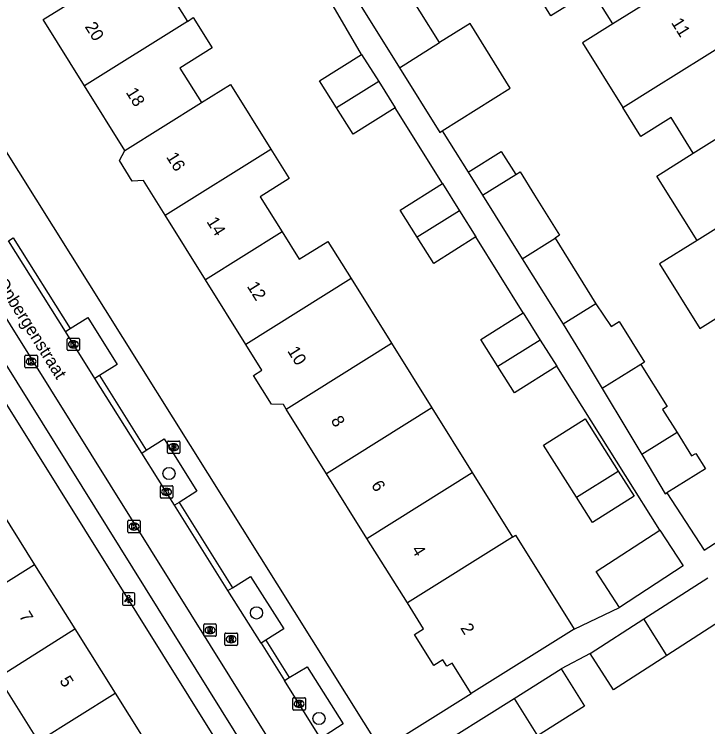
# Model space of a CAD drawing. Extents: x 159353 to 160616, y 385893 to 387321.
# Drawn here: x 159751.8 to 159807.5, y 386153.3 to 386210.6 of the extents above; entities that cross this region are included whole.
import ezdxf

# ---------------------------------------------------------------- set-up
doc = ezdxf.new("R2010")
doc.units = 0
for name, color, linetype in [('IMGEO_Boom', 7, 'Continuous'), ('IMGEO_Brandkraan', 7, 'Continuous'), ('IMGEO_Kolk', 7, 'Continuous'), ('IMGEO_Lichtpunt', 7, 'Continuous'), ('IMGEO_Openbare_ruimte_label', 7, 'Continuous'), ('IMGEO_Pand', 7, 'Continuous'), ('IMGEO_Pand_nummerreeks', 7, 'Continuous'), ('IMGEO_Rijbaan_lokaal_open', 7, 'Continuous'), ('IMGEO_Rioolput', 7, 'Continuous'), ('IMGEO_Voetpad_open', 7, 'Continuous')]:
    doc.layers.add(name, color=color, linetype=linetype)

msp = doc.modelspace()

# ---------------------------------------------------------------- linework, layer by layer
at = {"layer": 'IMGEO_Boom'}
for centre in [(159764.26, 386173.664), (159771.288, 386162.469), (159776.31, 386153.988)]:
    msp.add_circle(centre, 0.489, dxfattribs=at)
at = {"layer": 'IMGEO_Brandkraan'}
for p, q in [((159764.131, 386175.348), (159764.131, 386176.2)), ((159764.206, 386176.274), (159765.058, 386176.274)), ((159764.619, 386176.054), (159764.644, 386176.054)), ((159765.132, 386176.2), (159765.132, 386175.348)), ((159765.058, 386175.274), (159764.206, 386175.274)), ((159764.642, 386175.494), (159764.617, 386175.494))]:
    msp.add_line(p, q, dxfattribs=at)
for points in [[(159764.131, 386175.348), (159764.131, 386176.2)], [(159764.206, 386176.274), (159765.058, 386176.274)], [(159764.479, 386175.974), (159764.479, 386175.574), (159764.692, 386175.574)], [(159764.71, 386175.974), (159764.479, 386175.974)], [(159764.658, 386175.893), (159764.604, 386175.893), (159764.604, 386175.817)], [(159764.604, 386175.817), (159764.657, 386175.817)], [(159765.132, 386176.2), (159765.132, 386175.348)], [(159765.058, 386175.274), (159764.206, 386175.274)], [(159764.666, 386175.741), (159764.604, 386175.741), (159764.604, 386175.66)], [(159764.604, 386175.66), (159764.666, 386175.66)]]:
    msp.add_lwpolyline(points, dxfattribs=at)
for centre, radius, start, end in [((159764.208, 386176.198), 0.0765, 91.552, 178.448), ((159764.208, 386176.198), 0.0765, 91.552, 178.448), ((159764.659, 386175.855), 0.0379, 267.8285, 90.9355), ((159764.714, 386175.829), 0.145, 59.4692, 91.5367), ((159764.739, 386175.876), 0.0922, 285.5137, 58.1501), ((159764.744, 386175.684), 0.105, 301.3115, 78.989), ((159765.056, 386176.198), 0.0765, 1.552, 88.448), ((159765.056, 386176.198), 0.0765, 1.552, 88.448), ((159764.208, 386175.35), 0.0765, 181.552, 268.448), ((159764.208, 386175.35), 0.0765, 181.552, 268.448), ((159764.667, 386175.7), 0.0404, 269.8759, 90.5077), ((159764.698, 386175.825), 0.251, 268.6676, 293.5347), ((159765.056, 386175.35), 0.0765, 271.552, 358.448), ((159765.056, 386175.35), 0.0765, 271.552, 358.448)]:
    msp.add_arc(centre, radius, start, end, dxfattribs=at)
for centre, major_axis, ratio, start_param, end_param in [((159764.618, 386175.774), (-0.387, 0.002), 0.722429, 4.712389, 7.853982), ((159764.643, 386175.774), (-0.39, 0.002), 0.717154, 1.570796, 4.712389)]:
    msp.add_ellipse(centre, major_axis=major_axis, ratio=ratio, start_param=start_param, end_param=end_param, dxfattribs=at)
at = {"layer": 'IMGEO_Kolk'}
for p, q in [((159756.075, 386183.615), (159756.075, 386184.467)), ((159756.15, 386184.541), (159757.002, 386184.541)), ((159757.076, 386184.467), (159757.076, 386183.615)), ((159756.563, 386184.321), (159756.588, 386184.321)), ((159757.002, 386183.541), (159756.15, 386183.541)), ((159756.586, 386183.761), (159756.561, 386183.761)), ((159752.683, 386182.239), (159752.683, 386183.091)), ((159752.758, 386183.165), (159753.61, 386183.165)), ((159753.171, 386182.945), (159753.196, 386182.945)), ((159753.684, 386183.091), (159753.684, 386182.239)), ((159753.61, 386182.165), (159752.758, 386182.165)), ((159753.194, 386182.385), (159753.169, 386182.385)), ((159763.563, 386171.761), (159763.563, 386172.613)), ((159763.638, 386172.687), (159764.49, 386172.687)), ((159764.051, 386172.467), (159764.076, 386172.467)), ((159764.564, 386172.613), (159764.564, 386171.761)), ((159764.074, 386171.907), (159764.049, 386171.907)), ((159764.49, 386171.687), (159763.638, 386171.687)), ((159760.949, 386168.981), (159760.949, 386169.833)), ((159761.024, 386169.907), (159761.876, 386169.907)), ((159761.437, 386169.687), (159761.462, 386169.687)), ((159761.95, 386169.833), (159761.95, 386168.981)), ((159761.876, 386168.907), (159761.024, 386168.907)), ((159761.46, 386169.127), (159761.435, 386169.127)), ((159774.217, 386154.734), (159774.217, 386155.586)), ((159774.292, 386155.66), (159775.144, 386155.66)), ((159774.705, 386155.44), (159774.73, 386155.44)), ((159775.218, 386155.586), (159775.218, 386154.734)), ((159775.144, 386154.66), (159774.292, 386154.66)), ((159774.728, 386154.88), (159774.703, 386154.88))]:
    msp.add_line(p, q, dxfattribs=at)
for points in [[(159756.075, 386183.615), (159756.075, 386184.467)], [(159756.15, 386184.541), (159757.002, 386184.541)], [(159757.076, 386184.467), (159757.076, 386183.615)], [(159756.396, 386184.241), (159756.519, 386184.241), (159756.519, 386184.09), (159756.649, 386184.241), (159756.813, 386184.241), (159756.667, 386184.09), (159756.82, 386183.841), (159756.668, 386183.841), (159756.583, 386184.005), (159756.519, 386183.938), (159756.519, 386183.841), (159756.396, 386183.841), (159756.396, 386184.241)], [(159757.002, 386183.541), (159756.15, 386183.541)], [(159752.683, 386182.239), (159752.683, 386183.091)], [(159752.758, 386183.165), (159753.61, 386183.165)], [(159753.004, 386182.865), (159753.127, 386182.865), (159753.127, 386182.714), (159753.257, 386182.865), (159753.421, 386182.865), (159753.275, 386182.714), (159753.428, 386182.465), (159753.276, 386182.465), (159753.191, 386182.629), (159753.127, 386182.562), (159753.127, 386182.465), (159753.004, 386182.465), (159753.004, 386182.865)], [(159753.684, 386183.091), (159753.684, 386182.239)], [(159753.61, 386182.165), (159752.758, 386182.165)], [(159763.563, 386171.761), (159763.563, 386172.613)], [(159763.638, 386172.687), (159764.49, 386172.687)], [(159763.884, 386172.387), (159764.007, 386172.387), (159764.007, 386172.236), (159764.137, 386172.387), (159764.301, 386172.387), (159764.155, 386172.236), (159764.308, 386171.987), (159764.156, 386171.987), (159764.071, 386172.151), (159764.007, 386172.084), (159764.007, 386171.987), (159763.884, 386171.987), (159763.884, 386172.387)], [(159764.564, 386172.613), (159764.564, 386171.761)], [(159764.49, 386171.687), (159763.638, 386171.687)], [(159760.949, 386168.981), (159760.949, 386169.833)], [(159761.024, 386169.907), (159761.876, 386169.907)], [(159761.27, 386169.607), (159761.393, 386169.607), (159761.393, 386169.456), (159761.523, 386169.607), (159761.687, 386169.607), (159761.541, 386169.456), (159761.694, 386169.207), (159761.542, 386169.207), (159761.457, 386169.371), (159761.393, 386169.304), (159761.393, 386169.207), (159761.27, 386169.207), (159761.27, 386169.607)], [(159761.95, 386169.833), (159761.95, 386168.981)], [(159761.876, 386168.907), (159761.024, 386168.907)], [(159774.217, 386154.734), (159774.217, 386155.586)], [(159774.292, 386155.66), (159775.144, 386155.66)], [(159774.538, 386155.36), (159774.661, 386155.36), (159774.661, 386155.209), (159774.791, 386155.36), (159774.955, 386155.36), (159774.809, 386155.209), (159774.962, 386154.96), (159774.81, 386154.96), (159774.725, 386155.124), (159774.661, 386155.057), (159774.661, 386154.96), (159774.538, 386154.96), (159774.538, 386155.36)], [(159775.218, 386155.586), (159775.218, 386154.734)], [(159775.144, 386154.66), (159774.292, 386154.66)]]:
    msp.add_lwpolyline(points, dxfattribs=at)
for centre, start, end in [((159756.152, 386184.465), 91.552, 178.448), ((159756.152, 386184.465), 91.552, 178.448), ((159757, 386184.465), 1.552, 88.448), ((159757, 386184.465), 1.552, 88.448), ((159756.152, 386183.617), 181.552, 268.448), ((159756.152, 386183.617), 181.552, 268.448), ((159757, 386183.617), 271.552, 358.448), ((159757, 386183.617), 271.552, 358.448), ((159752.76, 386183.089), 91.552, 178.448), ((159752.76, 386183.089), 91.552, 178.448), ((159753.608, 386183.089), 1.552, 88.448), ((159753.608, 386183.089), 1.552, 88.448), ((159752.76, 386182.241), 181.552, 268.448), ((159752.76, 386182.241), 181.552, 268.448), ((159753.608, 386182.241), 271.552, 358.448), ((159753.608, 386182.241), 271.552, 358.448), ((159763.64, 386172.611), 91.552, 178.448), ((159763.64, 386172.611), 91.552, 178.448), ((159764.488, 386172.611), 1.552, 88.448), ((159764.488, 386172.611), 1.552, 88.448), ((159763.64, 386171.763), 181.552, 268.448), ((159763.64, 386171.763), 181.552, 268.448), ((159764.488, 386171.763), 271.552, 358.448), ((159764.488, 386171.763), 271.552, 358.448), ((159761.026, 386169.831), 91.552, 178.448), ((159761.026, 386169.831), 91.552, 178.448), ((159761.874, 386169.831), 1.552, 88.448), ((159761.874, 386169.831), 1.552, 88.448), ((159761.026, 386168.983), 181.552, 268.448), ((159761.026, 386168.983), 181.552, 268.448), ((159761.874, 386168.983), 271.552, 358.448), ((159761.874, 386168.983), 271.552, 358.448), ((159774.294, 386155.584), 91.552, 178.448), ((159774.294, 386155.584), 91.552, 178.448), ((159775.142, 386155.584), 1.552, 88.448), ((159775.142, 386155.584), 1.552, 88.448), ((159774.294, 386154.736), 181.552, 268.448), ((159774.294, 386154.736), 181.552, 268.448), ((159775.142, 386154.736), 271.552, 358.448), ((159775.142, 386154.736), 271.552, 358.448)]:
    msp.add_arc(centre, 0.0765, start, end, dxfattribs=at)
for centre, major_axis, ratio, start_param, end_param in [((159756.562, 386184.041), (-0.387, 0.002), 0.722429, 4.712389, 7.853982), ((159756.587, 386184.041), (-0.39, 0.002), 0.717154, 1.570796, 4.712389), ((159753.17, 386182.665), (-0.387, 0.002), 0.722429, 4.712389, 7.853982), ((159753.195, 386182.665), (-0.39, 0.002), 0.717154, 1.570796, 4.712389), ((159764.05, 386172.187), (-0.387, 0.002), 0.722429, 4.712389, 7.853982), ((159764.075, 386172.187), (-0.39, 0.002), 0.717154, 1.570796, 4.712389), ((159761.436, 386169.407), (-0.387, 0.002), 0.722429, 4.712389, 7.853982), ((159761.461, 386169.407), (-0.39, 0.002), 0.717154, 1.570796, 4.712389), ((159774.704, 386155.16), (-0.387, 0.002), 0.722429, 4.712389, 7.853982), ((159774.729, 386155.16), (-0.39, 0.002), 0.717154, 1.570796, 4.712389)]:
    msp.add_ellipse(centre, major_axis=major_axis, ratio=ratio, start_param=start_param, end_param=end_param, dxfattribs=at)
at = {"layer": 'IMGEO_Lichtpunt'}
for p, q in [((159760.515, 386163.99), (159760.515, 386163.183)), ((159760.515, 386163.99), (159760.515, 386163.183)), ((159761.417, 386164.085), (159760.609, 386164.085)), ((159761.417, 386164.085), (159760.609, 386164.085)), ((159761.511, 386163.183), (159761.511, 386163.99)), ((159761.511, 386163.183), (159761.511, 386163.99)), ((159760.609, 386163.089), (159761.417, 386163.089)), ((159760.609, 386163.089), (159761.417, 386163.089))]:
    msp.add_line(p, q, dxfattribs=at)
for points in [[(159760.889, 386163.654), (159760.928, 386163.626), (159760.74, 386163.364), (159760.702, 386163.391), (159760.889, 386163.654)], [(159760.991, 386163.606), (159761.038, 386163.606), (159761.038, 386163.284), (159760.991, 386163.284), (159760.991, 386163.606)], [(159761.101, 386163.626), (159761.139, 386163.653), (159761.326, 386163.391), (159761.287, 386163.363), (159761.101, 386163.626)]]:
    msp.add_lwpolyline(points, dxfattribs=at)
msp.add_circle((159761.014, 386163.788), 0.0994, dxfattribs=at)
for centre, start, end in [((159760.609, 386163.99), 90, 180), ((159760.609, 386163.99), 90, 180), ((159761.417, 386163.99), 0, 90), ((159761.417, 386163.99), 0, 90), ((159760.609, 386163.183), 180, 270), ((159760.609, 386163.183), 180, 270), ((159761.417, 386163.183), 270, 0), ((159761.417, 386163.183), 270, 360)]:
    msp.add_arc(centre, 0.0946, start, end, dxfattribs=at)
at = {"layer": 'IMGEO_Pand'}
for points in [[(159757.464, 386204.805), (159754.14, 386210.126), (159757.508, 386212.23), (159755.734, 386215.072), (159759.813, 386217.62), (159761.735, 386214.54), (159762.567, 386215.059), (159765.736, 386209.983)], [(159806.098, 386213.64), (159799.918, 386209.775)], [(159786.004, 386208.282), (159782.839, 386213.345), (159779.607, 386211.324)], [(159799.918, 386209.775), (159798.228, 386212.484), (159794.952, 386210.43), (159793.409, 386212.904), (159794.046, 386213.312)], [(159779.607, 386211.324), (159782.771, 386206.262)], [(159765.736, 386209.983), (159766.213, 386210.282), (159767.73, 386207.852), (159765.143, 386206.231), (159766.868, 386203.467)], [(159765.736, 386209.983), (159757.464, 386204.805)], [(159786.216, 386201.187), (159791.685, 386204.605), (159788.448, 386209.81), (159786.004, 386208.282)], [(159799.918, 386209.775), (159797.489, 386208.256), (159800.727, 386203.064)], [(159800.727, 386203.064), (159803.152, 386204.589), (159809.339, 386208.458)], [(159782.771, 386206.262), (159786.004, 386208.282)], [(159777.715, 386203.028), (159776.348, 386205.199), (159779.736, 386207.334)], [(159779.736, 386207.334), (159781.112, 386205.152)], [(159782.771, 386206.262), (159786.02, 386201.064), (159786.216, 386201.187)], [(159781.112, 386205.152), (159777.715, 386203.028)], [(159781.112, 386205.152), (159782.436, 386203.051)], [(159760.706, 386199.614), (159757.464, 386204.805)], [(159766.868, 386203.467), (159769.19, 386204.918), (159772.432, 386199.725)], [(159760.706, 386199.614), (159766.868, 386203.467)], [(159806.387, 386199.403), (159812.581, 386203.275)], [(159782.436, 386203.051), (159779.047, 386200.915), (159777.715, 386203.028)], [(159806.387, 386199.403), (159804.61, 386202.251), (159802.183, 386200.728), (159800.727, 386203.064)], [(159763.95, 386194.422), (159762.216, 386197.197), (159761.308, 386197.16), (159760.274, 386198.814), (159760.706, 386199.614)], [(159763.95, 386194.422), (159772.432, 386199.725)], [(159772.432, 386199.725), (159773.913, 386197.353), (159771.593, 386195.898), (159773.352, 386193.08)], [(159788.288, 386197.868), (159790.961, 386199.537), (159792.117, 386197.686)], [(159806.691, 386192.385), (159803.462, 386197.562), (159806.387, 386199.403)], [(159815.821, 386198.094), (159806.691, 386192.385)], [(159788.288, 386197.868), (159789.444, 386196.017)], [(159789.444, 386196.017), (159792.117, 386197.686)], [(159792.117, 386197.686), (159792.463, 386197.899), (159793.635, 386196.021), (159795.646, 386192.8), (159795.293, 386192.579)], [(159784.203, 386192.643), (159782.835, 386194.814), (159786.223, 386196.949)], [(159786.223, 386196.949), (159787.599, 386194.766)], [(159789.444, 386196.017), (159792.629, 386190.916)], [(159787.599, 386194.766), (159784.203, 386192.643)], [(159787.599, 386194.766), (159788.923, 386192.666)], [(159767.194, 386189.229), (159763.95, 386194.422)], [(159773.352, 386193.08), (159767.194, 386189.229)], [(159773.352, 386193.08), (159774.728, 386190.876), (159777.016, 386192.312), (159778.884, 386189.318)], [(159788.923, 386192.666), (159785.534, 386190.53), (159784.203, 386192.643)], [(159792.629, 386190.916), (159795.293, 386192.579)], [(159795.293, 386192.579), (159798.563, 386187.303)], [(159806.691, 386192.385), (159803.682, 386190.503), (159806.922, 386185.321), (159809.925, 386187.199)], [(159792.629, 386190.916), (159795.941, 386185.664)], [(159770.437, 386184.037), (159767.194, 386189.229)], [(159778.884, 386189.318), (159770.437, 386184.037)], [(159778.884, 386189.318), (159782.126, 386184.126)], [(159798.563, 386187.303), (159795.941, 386185.664)], [(159798.563, 386187.303), (159799.788, 386185.479), (159800.433, 386185.882), (159802.473, 386182.616), (159802.182, 386182.435)], [(159790.688, 386182.26), (159789.322, 386184.429), (159792.71, 386186.564)], [(159792.71, 386186.564), (159794.085, 386184.384)], [(159795.941, 386185.664), (159797.526, 386183.027), (159799.056, 386180.482)], [(159794.085, 386184.384), (159790.688, 386182.26)], [(159794.085, 386184.384), (159795.41, 386182.281)], [(159773.68, 386178.845), (159773.454, 386179.207), (159772.507, 386179.227), (159771.059, 386181.545), (159771.731, 386181.965), (159770.437, 386184.037)], [(159773.68, 386178.845), (159782.126, 386184.126)], [(159782.126, 386184.126), (159785.367, 386178.932)], [(159795.41, 386182.281), (159792.021, 386180.145), (159790.688, 386182.26)], [(159802.182, 386182.435), (159799.056, 386180.482)], [(159802.182, 386182.435), (159804.3, 386179.044), (159803.925, 386178.81), (159805.08, 386176.96)], [(159799.056, 386180.482), (159801.116, 386177.055), (159802.24, 386175.184)], [(159776.924, 386173.652), (159773.68, 386178.845)], [(159785.367, 386178.932), (159776.924, 386173.652)], [(159785.367, 386178.932), (159788.609, 386173.739)], [(159796.992, 386171.759), (159794.35, 386175.94), (159797.698, 386178.056), (159800.351, 386173.859)], [(159805.08, 386176.96), (159802.24, 386175.184)], [(159805.08, 386176.96), (159806.255, 386175.079), (159806.587, 386175.286), (159807.36, 386174.049), (159804.267, 386172.115)], [(159802.24, 386175.184), (159804.13, 386172.041), (159804.135, 386172.032), (159804.267, 386172.115)], [(159780.167, 386168.46), (159776.924, 386173.652)], [(159780.167, 386168.46), (159788.609, 386173.739)], [(159788.609, 386173.739), (159791.851, 386168.545)], [(159800.351, 386173.859), (159801.629, 386171.836), (159798.281, 386169.72), (159796.992, 386171.759)], [(159796.992, 386171.759), (159800.351, 386173.859)], [(159750.204, 386171.504), (159753.445, 386166.345)], [(159800.45, 386162.907), (159798.571, 386165.786), (159803.686, 386169.124)], [(159803.686, 386169.124), (159805.564, 386166.245), (159800.45, 386162.907)], [(159783.411, 386163.268), (159780.167, 386168.46)], [(159791.851, 386168.545), (159783.411, 386163.268)], [(159791.851, 386168.545), (159792.11, 386168.707), (159796.821, 386161.165)], [(159753.445, 386166.345), (159747.291, 386162.476)], [(159753.445, 386166.345), (159756.687, 386161.185)], [(159802.408, 386161.984), (159807.55, 386165.297)], [(159788.543, 386155.995), (159787.012, 386158.446), (159786.588, 386158.181), (159786.265, 386158.698), (159785.544, 386158.248), (159783.978, 386160.736), (159784.708, 386161.192), (159783.411, 386163.268)], [(159809.39, 386162.36), (159804.249, 386159.047)], [(159798.107, 386159.213), (159802.408, 386161.984)], [(159804.249, 386159.047), (159802.408, 386161.984)], [(159750.533, 386157.316), (159756.687, 386161.185)], [(159756.687, 386161.185), (159759.928, 386156.026)], [(159796.821, 386161.165), (159788.543, 386155.995)], [(159804.249, 386159.047), (159799.984, 386156.3), (159798.107, 386159.213)], [(159791.981, 386155.602), (159795.764, 386157.98)], [(159795.764, 386157.98), (159797.654, 386154.974), (159793.866, 386152.593)], [(159753.774, 386152.157), (159750.533, 386157.316)], [(159753.774, 386152.157), (159759.928, 386156.026)], [(159759.928, 386156.026), (159763.17, 386150.866)], [(159784.903, 386151.153), (159791.981, 386155.602)], [(159791.981, 386155.602), (159793.866, 386152.593)]]:
    msp.add_lwpolyline(points, dxfattribs=at)
at = {"layer": 'IMGEO_Rijbaan_lokaal_open'}
for points in [[(159788.47, 386126.403), (159741.92, 386200.989)], [(159755.937, 386185.075), (159751.368, 386192.352)], [(159758.308, 386181.306), (159755.937, 386185.075)], [(159762.065, 386175.311), (159758.308, 386181.306)], [(159764.702, 386171.113), (159762.065, 386175.311)], [(159768.984, 386164.269), (159764.702, 386171.113)], [(159771.654, 386160.035), (159768.984, 386164.269)], [(159771.654, 386160.035), (159773.531, 386157.033)], [(159776.428, 386152.399), (159773.531, 386157.033)]]:
    msp.add_lwpolyline(points, dxfattribs=at)
at = {"layer": 'IMGEO_Rioolput'}
for p, q in [((159767.054, 386160.665), (159767.054, 386161.517)), ((159767.129, 386161.591), (159767.981, 386161.591)), ((159768.055, 386161.517), (159768.055, 386160.665)), ((159767.542, 386161.371), (159767.567, 386161.371)), ((159767.981, 386160.591), (159767.129, 386160.591)), ((159767.565, 386160.811), (159767.54, 386160.811)), ((159768.752, 386159.927), (159768.752, 386160.779)), ((159768.827, 386160.853), (159769.679, 386160.853)), ((159769.24, 386160.633), (159769.265, 386160.633)), ((159769.753, 386160.779), (159769.753, 386159.927)), ((159769.679, 386159.853), (159768.827, 386159.853)), ((159769.263, 386160.073), (159769.238, 386160.073))]:
    msp.add_line(p, q, dxfattribs=at)
for points in [[(159767.054, 386160.665), (159767.054, 386161.517)], [(159767.129, 386161.591), (159767.981, 386161.591)], [(159768.055, 386161.517), (159768.055, 386160.665)], [(159767.643, 386161.289), (159767.391, 386161.291), (159767.391, 386160.891)], [(159767.391, 386160.891), (159767.515, 386160.891), (159767.515, 386161.053), (159767.526, 386161.053)], [(159767.569, 386161.21), (159767.515, 386161.21), (159767.515, 386161.129)], [(159767.515, 386161.129), (159767.567, 386161.129)], [(159767.573, 386161.024), (159767.644, 386160.891), (159767.784, 386160.891), (159767.719, 386161.017)], [(159767.981, 386160.591), (159767.129, 386160.591)], [(159768.752, 386159.927), (159768.752, 386160.779)], [(159768.827, 386160.853), (159769.679, 386160.853)], [(159769.341, 386160.551), (159769.089, 386160.553), (159769.089, 386160.153)], [(159769.089, 386160.153), (159769.213, 386160.153), (159769.213, 386160.315), (159769.224, 386160.315)], [(159769.267, 386160.472), (159769.213, 386160.472), (159769.213, 386160.391)], [(159769.213, 386160.391), (159769.265, 386160.391)], [(159769.753, 386160.779), (159769.753, 386159.927)], [(159769.679, 386159.853), (159768.827, 386159.853)], [(159769.271, 386160.286), (159769.342, 386160.153), (159769.482, 386160.153), (159769.417, 386160.279)]]:
    msp.add_lwpolyline(points, dxfattribs=at)
for centre, radius, start, end in [((159767.131, 386161.515), 0.0765, 91.552, 178.448), ((159767.131, 386161.515), 0.0765, 91.552, 178.448), ((159767.979, 386161.515), 0.0765, 1.552, 88.448), ((159767.979, 386161.515), 0.0765, 1.552, 88.448), ((159767.525, 386161), 0.0533, 26.0293, 88.6989), ((159767.551, 386161.318), 0.19, 274.7715, 282.9687), ((159767.575, 386161.114), 0.0964, 77.0061, 93.1865), ((159767.589, 386161.171), 0.0378, 276.6634, 79.6772), ((159767.642, 386161.179), 0.109, 350.3612, 89.416), ((159767.64, 386161.179), 0.112, 277.5842, 350.9817), ((159767.624, 386160.964), 0.108, 29.5134, 73.7905), ((159767.131, 386160.667), 0.0765, 181.552, 268.448), ((159767.131, 386160.667), 0.0765, 181.552, 268.448), ((159767.979, 386160.667), 0.0765, 271.552, 358.448), ((159767.979, 386160.667), 0.0765, 271.552, 358.448), ((159768.829, 386160.777), 0.0765, 91.552, 178.448), ((159768.829, 386160.777), 0.0765, 91.552, 178.448), ((159769.223, 386160.262), 0.0533, 26.0293, 88.6989), ((159769.249, 386160.58), 0.19, 274.7715, 282.9687), ((159769.273, 386160.376), 0.0964, 77.0061, 93.1865), ((159769.287, 386160.433), 0.0378, 276.6634, 79.6772), ((159769.34, 386160.441), 0.109, 350.3612, 89.416), ((159769.338, 386160.441), 0.112, 277.5842, 350.9817), ((159769.322, 386160.226), 0.108, 29.5134, 73.7905), ((159769.677, 386160.777), 0.0765, 1.552, 88.448), ((159769.677, 386160.777), 0.0765, 1.552, 88.448), ((159768.829, 386159.929), 0.0765, 181.552, 268.448), ((159768.829, 386159.929), 0.0765, 181.552, 268.448), ((159769.677, 386159.929), 0.0765, 271.552, 358.448), ((159769.677, 386159.929), 0.0765, 271.552, 358.448)]:
    msp.add_arc(centre, radius, start, end, dxfattribs=at)
for centre, major_axis, ratio, start_param, end_param in [((159767.541, 386161.091), (-0.387, 0.002), 0.722429, 4.712389, 7.853982), ((159767.566, 386161.091), (-0.39, 0.002), 0.717154, 1.570796, 4.712389), ((159769.239, 386160.353), (-0.387, 0.002), 0.722429, 4.712389, 7.853982), ((159769.264, 386160.353), (-0.39, 0.002), 0.717154, 1.570796, 4.712389)]:
    msp.add_ellipse(centre, major_axis=major_axis, ratio=ratio, start_param=start_param, end_param=end_param, dxfattribs=at)
at = {"layer": 'IMGEO_Voetpad_open'}
for points in [[(159779.736, 386207.334), (159776.037, 386213.7)], [(159781.317, 386151.464), (159745.213, 386209.036), (159745.591, 386210.827)], [(159772.114, 386145.744), (159736.577, 386202.635), (159733.614, 386203.294)], [(159786.223, 386196.949), (159782.436, 386203.051)], [(159786.216, 386201.187), (159788.288, 386197.868)], [(159771.528, 386149.758), (159741.852, 386197.34)], [(159751.368, 386192.352), (159751.738, 386192.588), (159756.306, 386185.316)], [(159792.71, 386186.564), (159788.923, 386192.666)], [(159756.306, 386185.316), (159757.74, 386186.211), (159760.106, 386182.426), (159758.678, 386181.532)], [(159755.937, 386185.075), (159756.306, 386185.316)], [(159804.267, 386172.115), (159807.258, 386167.515), (159831.974, 386183.449)], [(159803.686, 386169.124), (159795.41, 386182.281)], [(159758.678, 386181.532), (159758.308, 386181.306)], [(159758.678, 386181.532), (159762.434, 386175.553)], [(159762.434, 386175.553), (159763.867, 386176.445), (159766.509, 386172.237), (159765.08, 386171.349)], [(159762.065, 386175.311), (159762.434, 386175.553)], [(159765.08, 386171.349), (159764.702, 386171.113)], [(159765.08, 386171.349), (159769.365, 386164.495)], [(159769.365, 386164.495), (159770.798, 386165.398), (159773.487, 386161.187), (159772.036, 386160.268)], [(159768.984, 386164.269), (159769.365, 386164.495)], [(159796.821, 386161.165), (159800.45, 386162.907)], [(159772.036, 386160.268), (159771.654, 386160.035)], [(159772.036, 386160.268), (159773.911, 386157.271)], [(159798.107, 386159.213), (159795.764, 386157.98)], [(159773.911, 386157.271), (159775.363, 386158.15), (159778.251, 386153.56), (159776.804, 386152.637)], [(159773.531, 386157.033), (159773.911, 386157.271)], [(159781.317, 386151.464), (159788.543, 386155.995)]]:
    msp.add_lwpolyline(points, dxfattribs=at)

# ---------------------------------------------------------------- texts
at = {"layer": 'IMGEO_Openbare_ruimte_label'}
msp.add_text('Anthony van Opbergenstraat', height=1, rotation=302.1329, dxfattribs=at).set_placement((159746.16, 386195.632))
at = {"layer": 'IMGEO_Pand_nummerreeks'}
for s, rotation, p in [('11', 302.0224, (159804.578, 386209.886)), ('20', 301.9914, (159757.464, 386209.562)), ('18', 301.9914, (159760.757, 386204.29)), ('16', 301.9914, (159764, 386199.098)), ('14', 301.9914, (159767.244, 386193.904)), ('12', 301.9914, (159770.488, 386188.712)), ('10', 301.9938, (159773.736, 386183.512)), ('8', 301.9914, (159777.225, 386177.927)), ('6', 301.9914, (159780.468, 386172.736)), ('4', 301.9914, (159783.712, 386167.541)), ('7', 302.1397, (159752.168, 386162.212)), ('2', 301.9861, (159787.638, 386161.257)), ('5', 302.1397, (159755.425, 386157.028))]:
    msp.add_text(s, height=1, rotation=rotation, dxfattribs=at).set_placement(p)

doc.saveas('drawing.dxf')
